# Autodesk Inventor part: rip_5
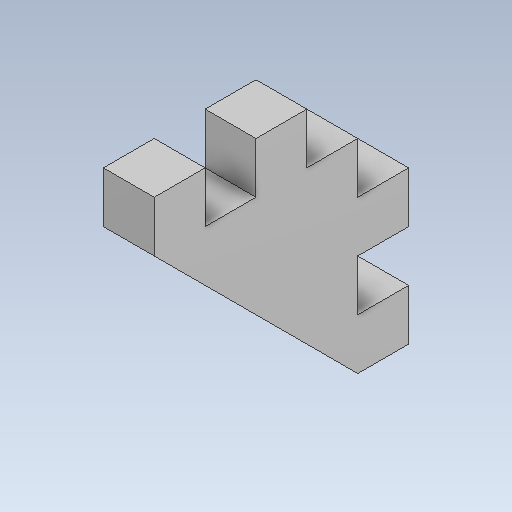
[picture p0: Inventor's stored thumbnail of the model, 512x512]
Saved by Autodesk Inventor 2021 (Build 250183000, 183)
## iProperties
Created: 2026-10
Part Number: rip_5
Material: Generic
Document SubType Name: Modeling
Designer: hp
Density: 1 g/cm^3
Appearance: Default
Author: hp
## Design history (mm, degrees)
feature "Body1"
body "Solid1"
